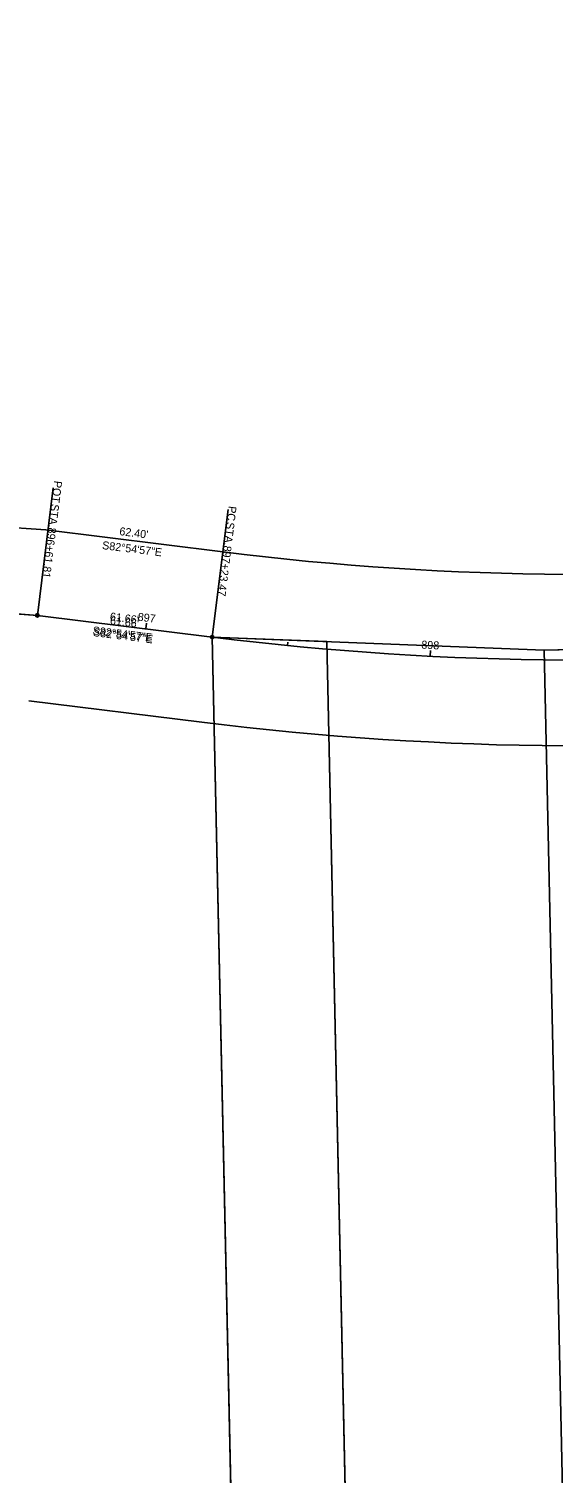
# Model space of a CAD drawing. Extents: x 2379325 to 2382869, y 256594 to 258871.
# Drawn here: x 2381889 to 2382073, y 257602 to 258107 of the extents above; entities that cross this region are included whole.
import ezdxf

# ---------------------------------------------------------------- set-up
doc = ezdxf.new("R2010")
doc.units = 0
for name, color, linetype in [('_CIVIL_CONSTRUCTION', 7, 'Continuous'), ('DR_P_Headwall', 7, 'Continuous'), ('DR_X_Culvert3D', 7, 'Continuous'), ('DR_X_Storm_Sewer', 7, 'Continuous'), ('GK_Drainage_Nodes', 7, 'Continuous'), ('PTS_GRAIL', 7, 'Continuous'), ('PTS_PVMT', 7, 'Continuous'), ('SC_Scratch2', 7, 'Continuous'), ('SC_Scratch3', 7, 'Continuous')]:
    doc.layers.add(name, color=color, linetype=linetype)

msp = doc.modelspace()

# ---------------------------------------------------------------- linework, layer by layer
at = {"layer": 'DR_P_Headwall'}
for p, q in [((2380917.79, 258004.56), (2381895.07, 257932.07)), ((2381895.07, 257932.07), (2381957, 257924.38)), ((2381889.15, 257872.35), (2381949.6, 257864.84))]:
    msp.add_line(p, q, dxfattribs=at)
for radius in [1030.16, 1090.16]:
    msp.add_arc((2382084.05, 258946.67), radius, 262.91573, 276.30412, dxfattribs=at)
at = {"layer": 'DR_X_Culvert3D'}
for p, q in [((2381930.01, 257897.5), (2381930.25, 257899.49)), ((2381979.66, 257891.66), (2381979.78, 257892.86)), ((2382029.52, 257887.92), (2382029.62, 257889.91))]:
    msp.add_line(p, q, dxfattribs=at)
at = {"layer": 'DR_X_Storm_Sewer'}
for p, q in [((2381965.34, 257342.36), (2381953.3, 257894.61)), ((2381953.3, 257894.61), (2382069.47, 257890.07)), ((2382005.44, 257338.25), (2381993.34, 257893.06)), ((2382069.47, 257890.07), (2382200.46, 257892.92)), ((2382081.8, 257324.85), (2382069.47, 257890.07))]:
    msp.add_line(p, q, dxfattribs=at)
at = {"layer": 'PTS_PVMT'}
for points in [[(2380915.57, 257974.64), (2381892.11, 257902.21), (2381953.3, 257894.61), (2382069.47, 257890.07), (2382200.46, 257892.92), (2382282.14, 257907.78), (2382270.85, 258207.56), (2382395.58, 258240.12), (2382408.52, 258119.54), (2382529.94, 258163.94), (2382565.45, 257993.51), (2382716.17, 258049.69), (2382661.23, 258620.32), (2382184.82, 258609.93), (2381665.09, 258580.43), (2381008.69, 258600.49), (2380481.9, 258662.85), (2379503.04, 258870.93), (2379508.92, 258601.15), (2380163.69, 258211.64)], [(2379552.68, 256594.47), (2382560.76, 256658.22), (2382539.23, 256806.67), (2382868.71, 256813.65), (2382750.56, 257628.63), (2382747.68, 257793.6), (2382735.36, 257850.36), (2382716.17, 258049.69), (2382565.45, 257993.51), (2382589.49, 257668.38), (2382380.71, 257630.58), (2382397.79, 257407.88), (2382212.4, 257345.31), (2382214.34, 257256.29), (2382081.8, 257324.85), (2382005.44, 257338.25), (2381993.34, 257893.06), (2381953.3, 257894.61), (2381965.34, 257342.36), (2381852.47, 257353.48)]]:
    msp.add_lwpolyline(points, dxfattribs=at)
at = {"layer": 'SC_Scratch2'}
for q in [(2380915.57, 257974.64), (2381953.3, 257894.61)]:
    msp.add_line((2381892.11, 257902.21), q, dxfattribs=at)
msp.add_arc((2382084.05, 258946.67), 1060.16, 262.91573, 276.30412, dxfattribs=at)
at = {"layer": 'SC_Scratch3'}
for p, q in [((2381892.11, 257902.21), (2381897.66, 257946.87)), ((2381953.3, 257894.61), (2381958.85, 257939.26))]:
    msp.add_line(p, q, dxfattribs=at)
for centre in [(2381892.11, 257902.21), (2381953.3, 257894.61)]:
    msp.add_circle(centre, 0.6, dxfattribs=at)

# ---------------------------------------------------------------- texts
at = {"layer": '_CIVIL_CONSTRUCTION'}
msp.add_text("61.66'", height=2.8, rotation=352.9157, dxfattribs=at).set_placement((2381917.43, 257899.1))
at = {"layer": 'DR_X_Culvert3D'}
for s, rotation, p in [('897', 352.9157, (2381927.1, 257900.38)), ('898', 357.0517, (2382026.4, 257890.58))]:
    msp.add_text(s, height=2.8, rotation=rotation, dxfattribs=at).set_placement(p)
at = {"layer": 'GK_Drainage_Nodes'}
msp.add_text('S82°54\'57"E', height=2.8, rotation=352.9157, dxfattribs=at).set_placement((2381911.49, 257894.97))
at = {"layer": 'PTS_GRAIL'}
for s, p in [('S82°54\'57"E', (2381914.66, 257925.41)), ("62.40'", (2381920.69, 257930.3)), ("61.66'", (2381917.36, 257900.48)), ('S82°54\'57"E', (2381911.33, 257895.59))]:
    msp.add_text(s, height=2.8, rotation=352.9157, dxfattribs=at).set_placement(p)
at = {"layer": 'SC_Scratch3'}
for s, p in [('POT', (2381898.01, 257949.4)), (' STA. ', (2381897.13, 257942.32)), ('PC', (2381959.05, 257940.56)), (' STA. ', (2381958.48, 257935.99)), ('896+61.81', (2381895.98, 257933.07)), ('897+23.47', (2381957.33, 257926.74))]:
    msp.add_text(s, height=2.8, rotation=262.9157, dxfattribs=at).set_placement(p)

doc.saveas('drawing.dxf')
